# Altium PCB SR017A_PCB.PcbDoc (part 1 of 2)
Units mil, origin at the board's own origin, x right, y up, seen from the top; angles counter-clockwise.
Board outline 3000 x 2501 mil, 4 copper layers (Top Layer, GND Layer, Signal Layer, Bottom Layer), stack 59.4 mil thick; 53 components, 14 nets, 94 pads, 180 vias.
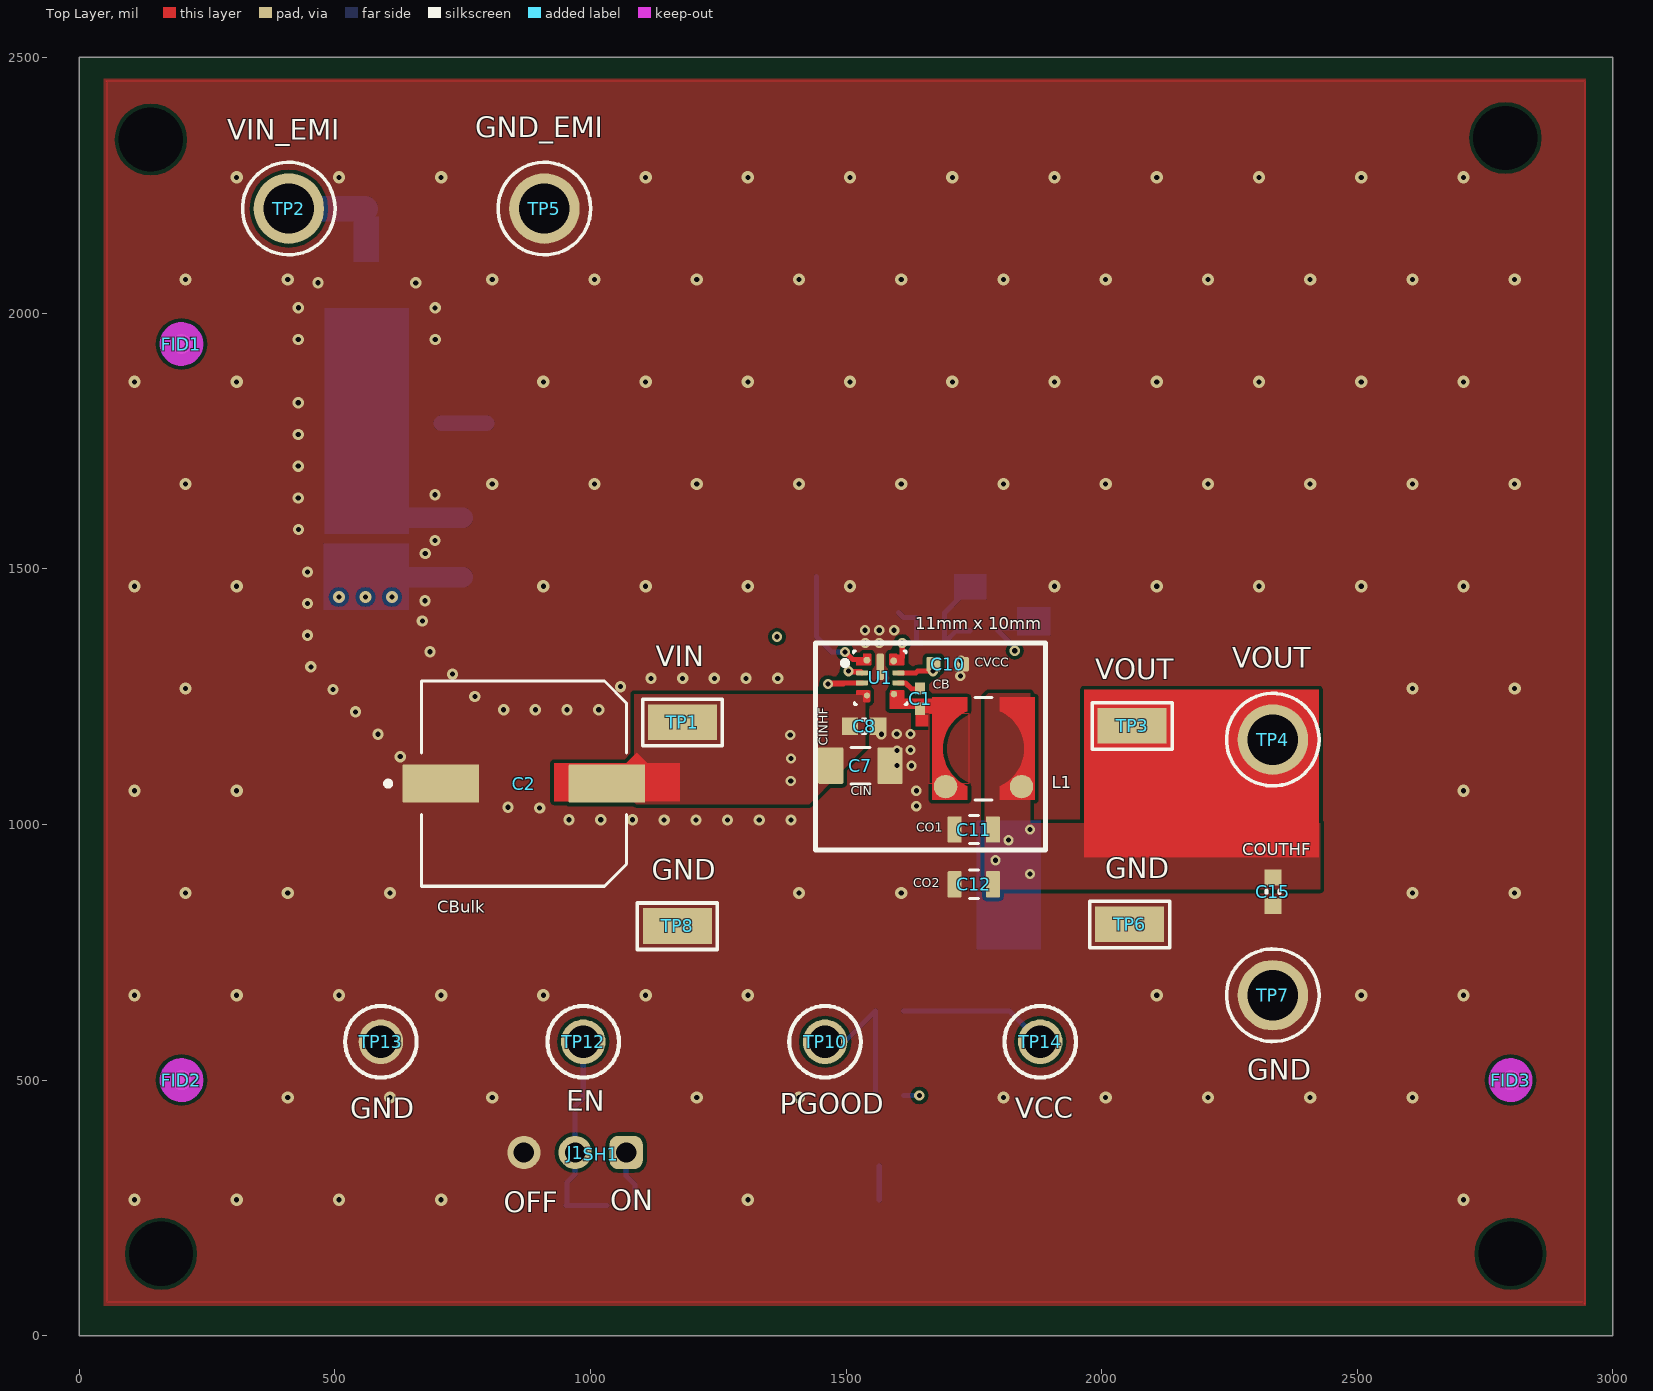
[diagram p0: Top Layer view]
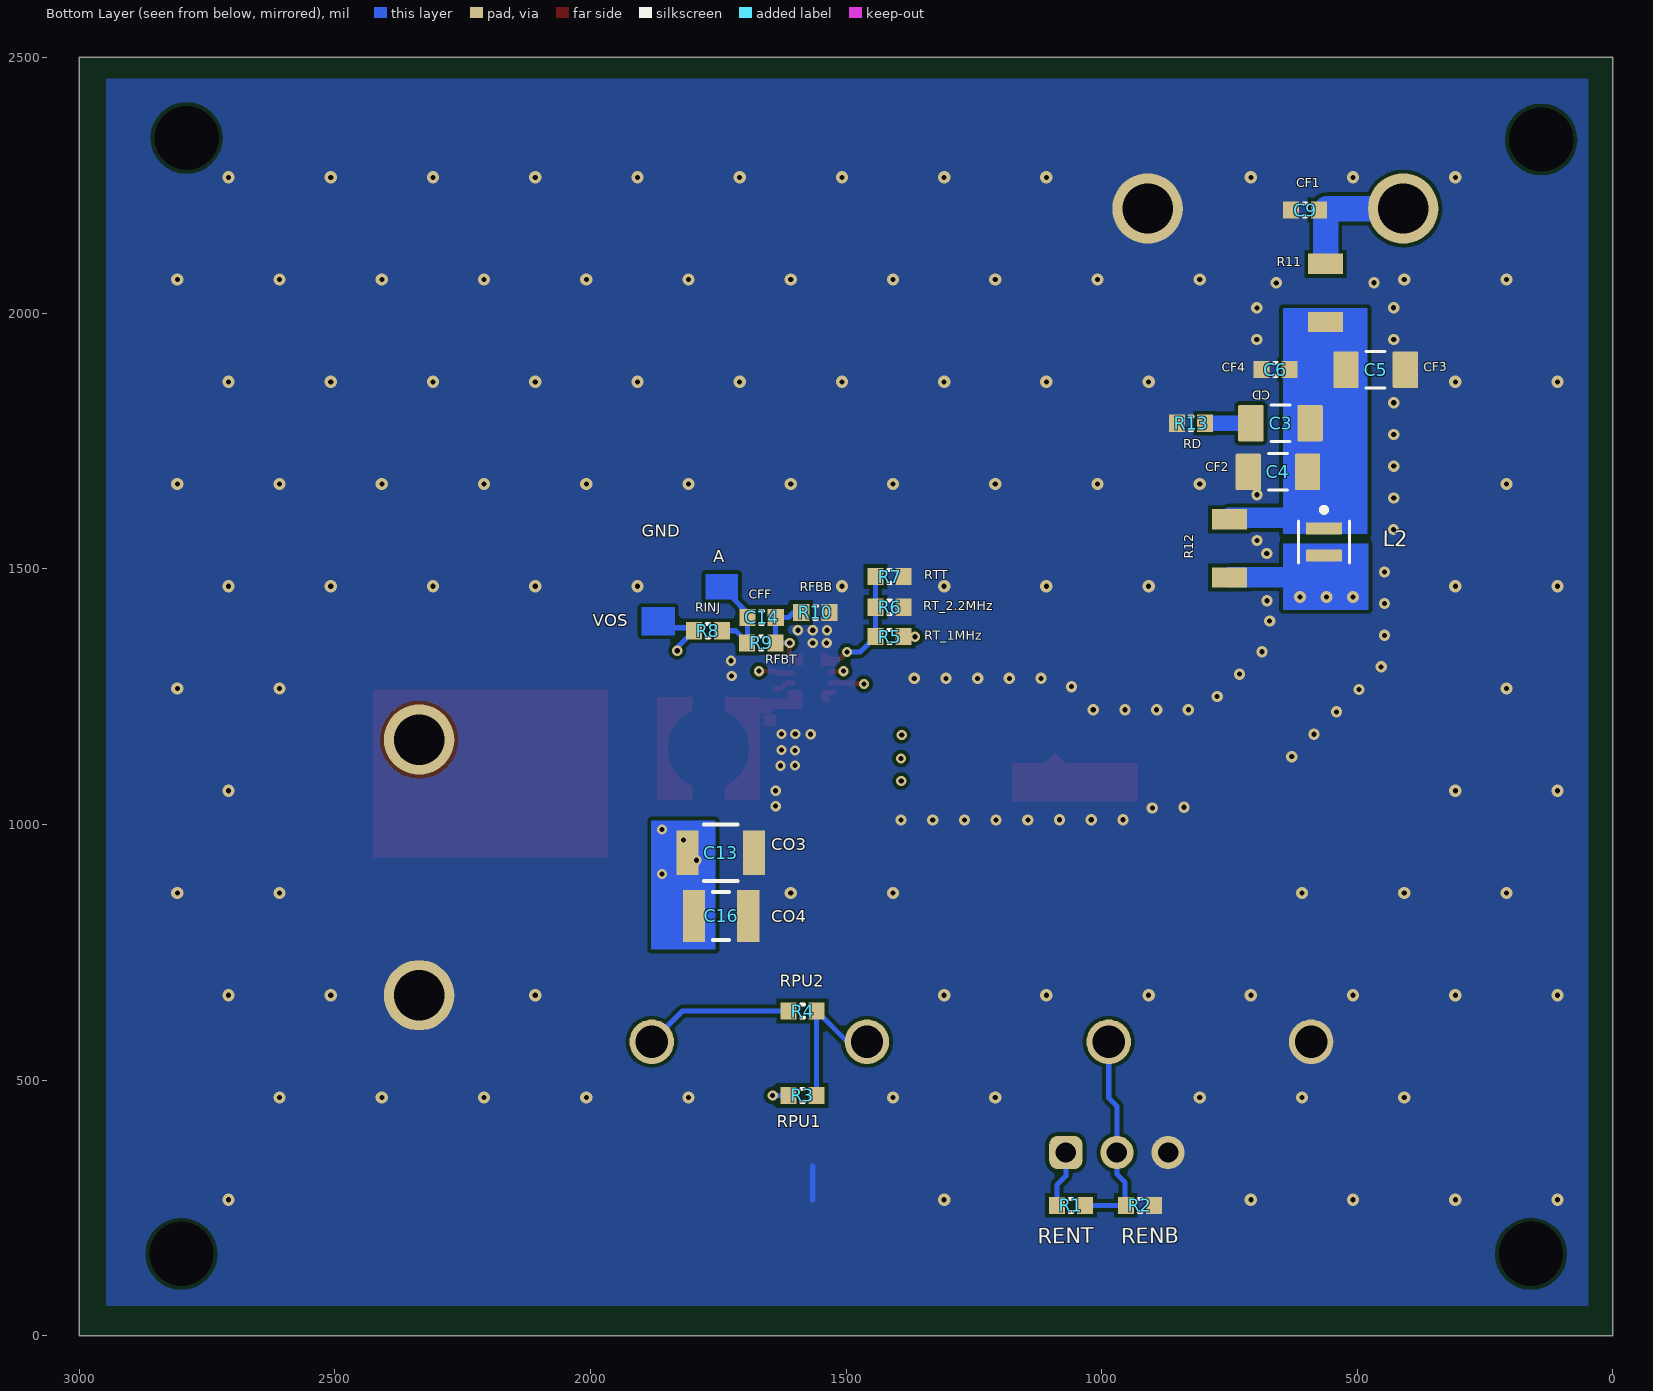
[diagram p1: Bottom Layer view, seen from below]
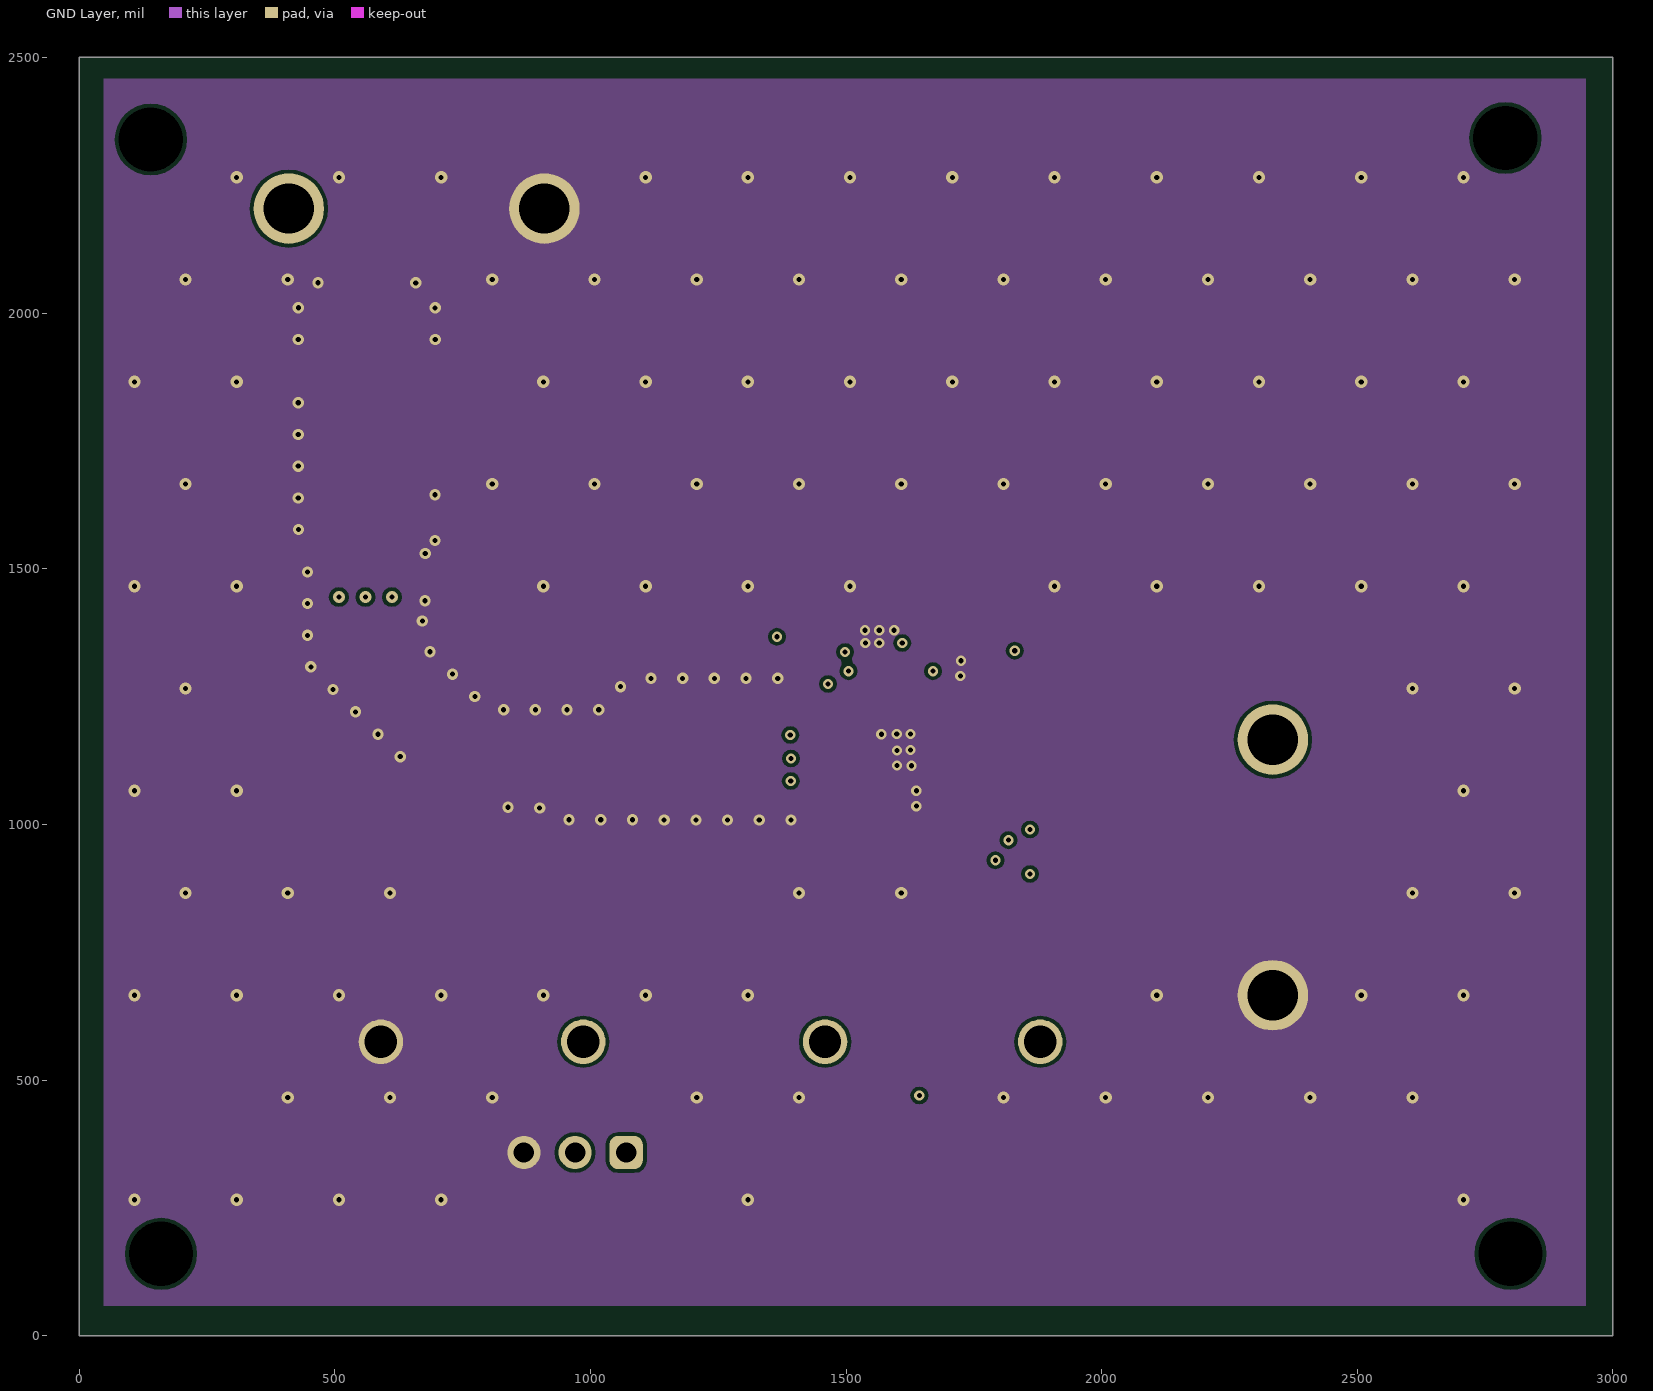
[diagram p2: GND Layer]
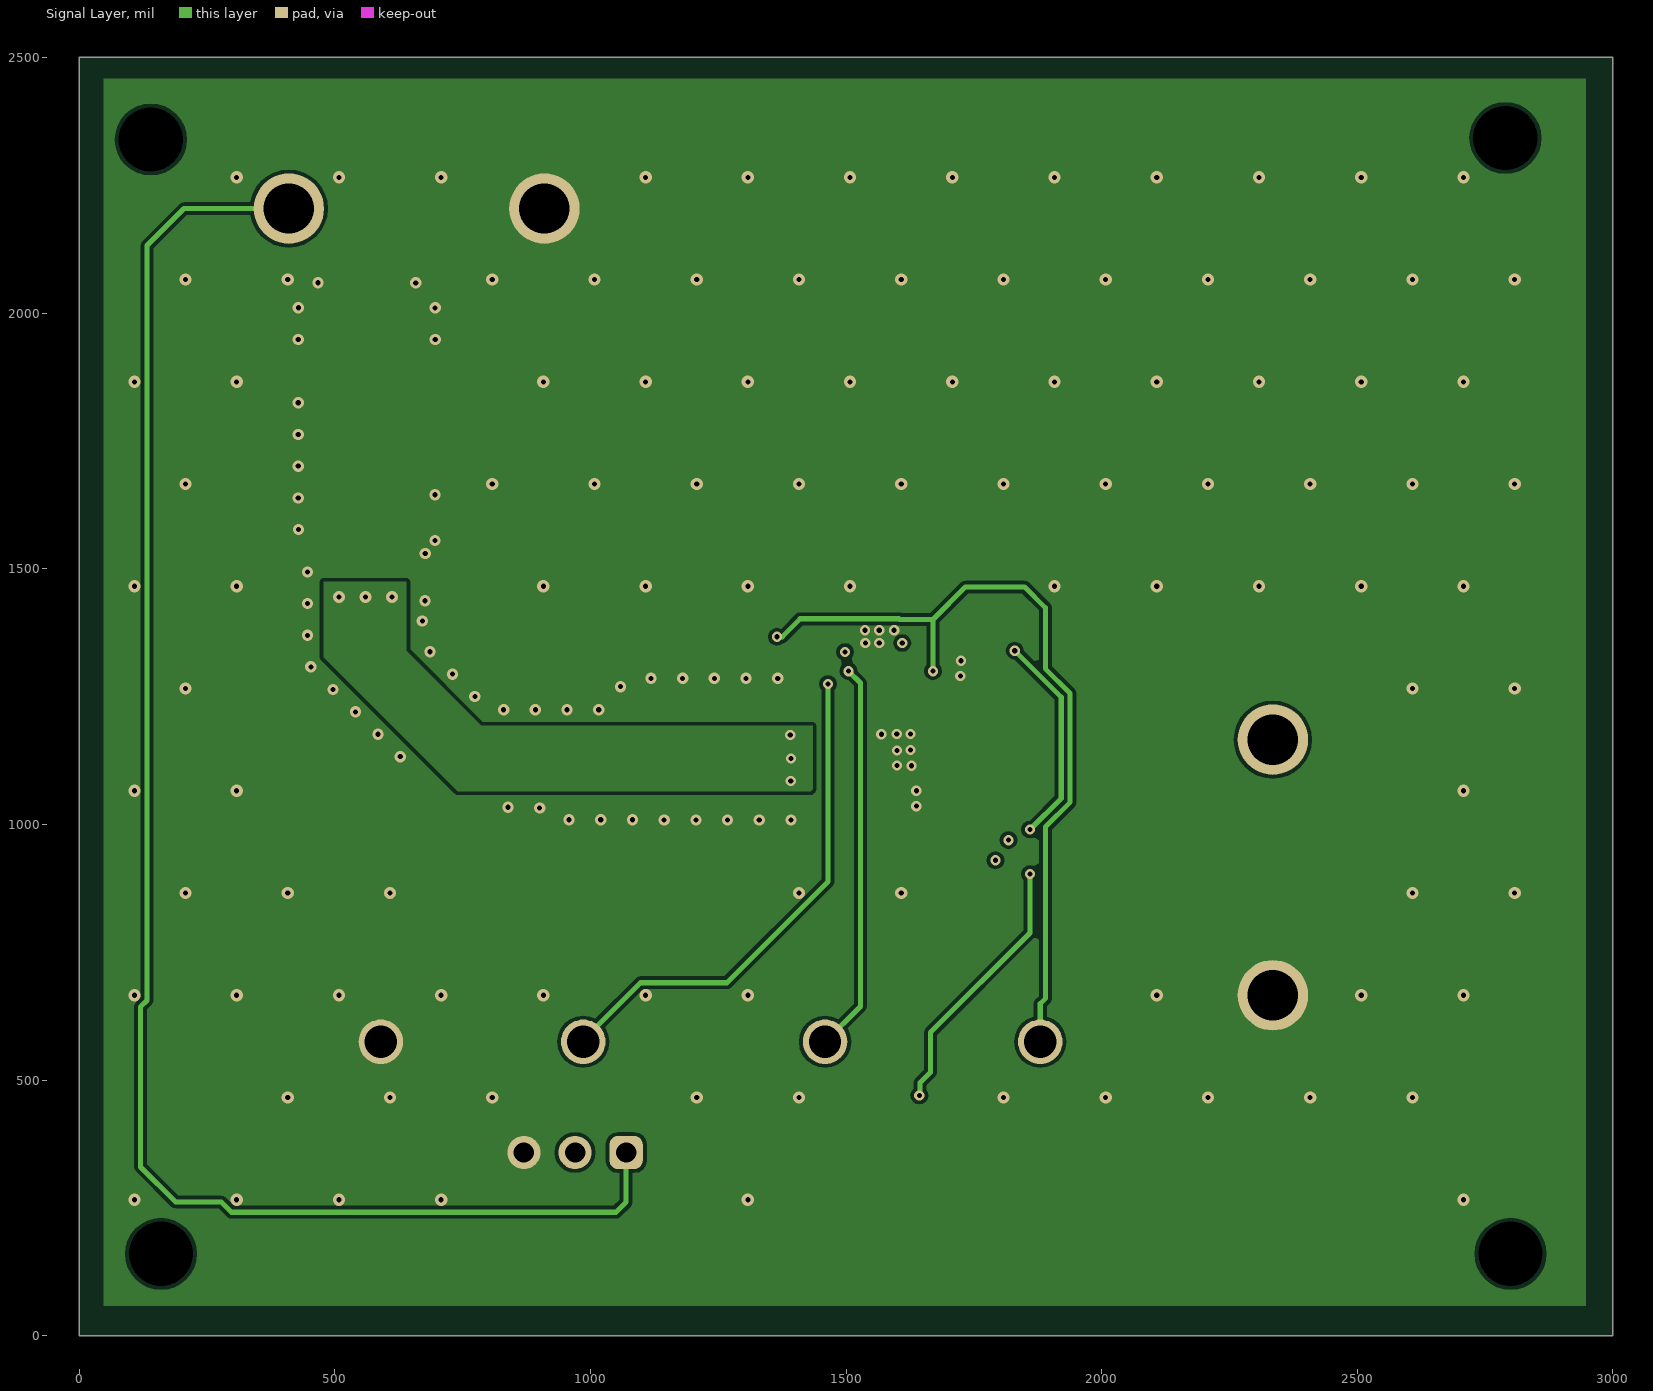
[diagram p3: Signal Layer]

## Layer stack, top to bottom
Top Solder: solder mask 0.4, Solder Resist, Dk 3.5
Top Layer: signal copper 2.8
Dielectric1: core 10, FR-4 High Tg, Dk 4.2
GND Layer: signal copper 1.4
Dielectric 2: prepreg 31, FR-4 High Tg, Dk 4.2
Signal Layer: signal copper 1.4
Dielectric 3: core 10, FR-4 High Tg, Dk 4.2
Bottom Layer: signal copper 2.8
Bottom Solder: solder mask 0.4, Solder Resist, Dk 3.5

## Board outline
0,0 0,2501 2999,2501 3000,2500 3000,0

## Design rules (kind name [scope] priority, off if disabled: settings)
AcuteAngle [All] p1: minimum=4.50000000000000E+0001 checktracksonly=FALSE
AssemblyTestPointUsage [All] p1: valid=2
BoardOutlineClearance BoardOutlineClearance_MountingHoles [OnCopper and InComponentClass('Mounting Holes')] p1: gap=40 ignorepadtopadclearanceinfootprint=FALSE
BoardOutlineClearance BoardOutlineClearance_Poly [OnCopper and IsPoly] p2: gap=25 ignorepadtopadclearanceinfootprint=FALSE
BoardOutlineClearance [OnCopper and Not InComponentClass('Logo') and not InComponentClass('FiducialMark') and not InRegion(1000,500,4000,800) and not InPoly] p3: gap=30 ignorepadtopadclearanceinfootprint=FALSE
Clearance Clearance_Keepouts [((IsTrack Or IsArc) And Not InPoly) And IsFree and IsKeepOut vs ((IsTrack Or IsArc) And Not InPoly) And IsFree and IsKeepOut] p1: gap=0 ignorepadtopadclearanceinfootprint=FALSE
Clearance Clearance_Poly [InPolygon] p2: gap=7 ignorepadtopadclearanceinfootprint=FALSE
Clearance Clearance_FiducialMark [IsKeepOut and InComponentClass('FiducialMark') vs IsPad and InComponentClass('FiducialMark')] p3: gap=0 ignorepadtopadclearanceinfootprint=FALSE
Clearance [All] p4: gap=7.5 ignorepadtopadclearanceinfootprint=FALSE except(0: Arc-Hole Track-Hole SMDPad-Hole THPad-Hole Via-Hole Fill-Hole Poly-Hole Region-Hole Text-Hole)
ComponentClearance ComponentClearance_MountingHoles_FiducialMarks [InComponentClass('Mounting Holes') vs InComponentClass('FiducialMark')] p1: gap=50 collisioncheckmode=3 verticalgap=10 showdistances=FALSE
ComponentClearance ComponentClearance_Shunt [InComponentClass('Header') vs InComponentClass('Shunt')] p2: gap=0 collisioncheckmode=3 verticalgap=0 showdistances=FALSE
ComponentClearance ComponentClearance_Logo [InComponentClass('Logo')] p3: gap=50 collisioncheckmode=3 verticalgap=10 showdistances=FALSE
ComponentClearance ComponentClearance_ScrewToNut [(HasFootprint('NY PMS 440 0025 PH')) vs (HasFootprint('Keystone_1902C'))] p4: gap=5 collisioncheckmode=3 verticalgap=10 showdistances=FALSE
ComponentClearance ComponentClearance_MountingHoles [InComponentClass('Mounting Holes')] p5: gap=250 collisioncheckmode=3 verticalgap=100000 showdistances=FALSE
ComponentClearance ComponentClearance_SmallPassives [HasFootprint('0201*') or HasFootprint('0402*') or HasFootprint('0508') or HasFootprint('0603*') or HasFootprint('0612') or HasFootprint('0805*') or HasFootprint('0815*') or HasFootprint('0830*') or HasFootprint('1206*') or HasFootprint('1210*') or HasFootprint('1808*') or HasFootprint('1812*') or HasFootprint('1825*') or HasFootprint('2010*') or HasFootprint('2220*') or HasFootprint('2225*') or HasFootprint('2512*') or HasFootprint('2728*') or HasFootprint('3518*') vs HasFootprint('0201*') or HasFootprint('0402*') or HasFootprint('0508') or HasFootprint('0603*') or HasFootprint('0612') or HasFootprint('0805*') or HasFootprint('0815*') or HasFootprint('0830*') or HasFootprint('1206*') or HasFootprint('1210*') or HasFootprint('1808*') or HasFootprint('1812*') or HasFootprint('1825*') or HasFootprint('2010*') or HasFootprint('2220*') or HasFootprint('2225*') or HasFootprint('2512*') or HasFootprint('2728*') or HasFootprint('3518*')] p6: gap=10 collisioncheckmode=3 verticalgap=10 showdistances=FALSE
ComponentClearance ComponentClearance_THtoSMT [IsThruComponent vs IsSMTComponent] p7: gap=40 collisioncheckmode=3 verticalgap=30 showdistances=FALSE
ComponentClearance ComponentClearance_THtoTH [IsThruComponent vs IsThruComponent] p8: gap=30 collisioncheckmode=3 verticalgap=30 showdistances=FALSE
ComponentClearance [All] p9: gap=10 collisioncheckmode=3 verticalgap=10 showdistances=FALSE
DiffPairsRouting [All] p1: maxlimit=100 minlimit=10 mostfreqgap=10 toplayer_minwidth=15 toplayer_maxwidth=15 toplayer_prefwidth=15 midlayer1_minwidth=15 midlayer1_maxwidth=15 midlayer1_prefwidth=15 midlayer2_minwidth=15 midlayer2_maxwidth=15 midlayer2_prefwidth=15 bottomlayer_minwidth=15 bottomlayer_maxwidth=15 bottomlayer_prefwidth=15 maxuncoupledlength=1000
FabricationTestPointUsage TestPointUsage [All] p1: valid=2 allowmultiple=FALSE
FabricationTestpoint Testpoint [All] p1: side=3 testpointundercomponent=TRUE minsize=40 maxsize=100 preferedsize=60 minholesize=0 maxholesize=40 preferedholesize=32 testpointgrid=1 allowsidetop=TRUE allowsidebottom=TRUE usegrid=TRUE gridtolerance=0.01
FanoutControl Fanout_LCC [IsLCC] p1: bgadir=Out bgaviamode=Centered fanoutstyle=Auto fanoutdirection=Alternating viagrid=1 // Fanout_LCC (Default Rule)
FanoutControl Fanout_BGA [IsBGA] p2: bgadir=Out bgaviamode=Centered fanoutstyle=Auto fanoutdirection=Alternating viagrid=1 // Fanout_BGA (Default Rule)
FanoutControl Fanout_Default [All] p4: bgadir=Out bgaviamode=Centered fanoutstyle=Auto fanoutdirection=Alternating viagrid=1 // Fanout_Default (Default Rule)
FanoutControl Fanout_Small [(CompPinCount < 5)] p5: bgadir=Out bgaviamode=Centered fanoutstyle=Auto fanoutdirection=OutThenIn viagrid=1 // Fanout_Small (Default Rule)
HoleSize [All] p1: absolutevalues=TRUE maxlimit=251 minlimit=7.87 maxpercent=80.000 minpercent=20.000
MinimumAnnularRing MinimumAnnularRing_ThermalPadVias [IsVia and InAnyComponent] p1: minimumring=5
MinimumAnnularRing [All] p2: minimumring=5
MinimumSolderMaskSliver MinimumSolderMaskSliver_Logo [InComponentClass('Logo') vs InComponentClass('Logo')] p1: minsoldermaskwidth=0.7
MinimumSolderMaskSliver [All] p2: minsoldermaskwidth=3.94
PlaneClearance [All] p1: clearance=8
PlaneConnect [All] p1: planeconnectstyle=Direct reliefexpansion=10 reliefentries=4 reliefconductorwidth=10 reliefairgap=10
PolygonConnect [All] p1: connectstyle=Direct reliefconductorwidth=10 reliefentries=4 polygonreliefangle="90 Angle" airgapwidth=10
RoutingVias ThermalPadVias [IsVia and InAnyComponent] p1: holewidth=8 width=16 viastyle="Through Hole" minholewidth=7.87 minwidth=10 maxholewidth=12.99 maxwidth=30
RoutingVias [All] p2: holewidth=8 width=16 viastyle="Through Hole" minholewidth=7.87 minwidth=15 maxholewidth=40 maxwidth=65
SilkToBoardRegionClearance [Not ((IsComment or IsDesignator) And (Hide <> 'False')) and not InRegion(1000,500,4000,800)] p1:
SilkToSilkClearance SilkToSilkClearance_Pb-FreeLogo [(HasFootprint('Pb-Free_Overlay_Medium') OR HasFootprint('Pb-Free_Overlay_Small')) vs (HasFootprint('Pb-Free_Overlay_Medium') OR HasFootprint('Pb-Free_Overlay_Small'))] p1: silktosilkclearance=0
SilkToSilkClearance [All] p2: silktosilkclearance=0
SilkToSolderMaskClearance SilkToComponentPadClearance [(IsPad or IsFill or IsRegion) and InAnycomponent] p1: minsilkscreentomaskgap=0 clearancetoexposedcopper=TRUE
SilkToSolderMaskClearance "Silk to Solder Mask Opening" [All] p2: minsilkscreentomaskgap=0 clearancetoexposedcopper=FALSE
SolderMaskExpansion [All] p1: expansion=1.97
Width [All] p1: maxlimit=100 minlimit=0.1 preferedwidth=10
14 further rules are at their usual default settings.

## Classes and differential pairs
component class Header: J1
component class FiducialMark: FID1 FID2 FID3
component class AssemblyNote: ZZ1 ZZ2 ZZ3 ZZ4
component class SR017A_sch: C1 C2 C3 C4 C5 C6 C7 C8 C9 C10 C11 C12 C13 C14 C15 C16 CVCC J1 L L1 L2 R1 R2 R3 R4 R5 R6 R7 R8 R9 R10 R11 R12 R13 R? SH1 TP1 TP2 TP3 TP4 TP5 TP6 TP7 TP8 TP10 TP12 TP13 TP14 U1
component class SR017A_Hardware: FID1 FID2 FID3 ZZ1 ZZ2 ZZ3 ZZ4
component class Shunt: SH1

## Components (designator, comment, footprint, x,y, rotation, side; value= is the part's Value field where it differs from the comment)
C1 "CB" 0402L 1644.8,1246.17 r90 top value=0.1uF
C2 "CBulk" FP-476SML100M_RADIAL-IPC_C 870,1080 r0 top value=47µF
C3 "CD" FP-CL31Y225KCHVPNE_1206-MFG 650,1785 r180 bottom value=2.2µF
C4 "CF2" FP-CL31Y225KCHVPNE_1206-MFG 655,1690 r180 bottom value=2.2µF
C5 "CF3" FP-CL31Y225KCHVPNE_1206-MFG 463.93,1889.7 r0 bottom value=2.2µF
C6 "CF4" 0603L 660,1890 r0 bottom value=0.1uF
C7 "CIN" FP-CL31Y225KCHVPNE_1206-MFG 1528.2,1115 r180 top value=2.2µF
C8 "CINHF" 0603L 1535.46,1192.13 r0 top value=0.1uF
C9 "CF1" 0603L 602,2202 r0 bottom value=0.1uF
C10 "CVCC" FP-C1608X7R1E105K080AE_0603-MFG 1698.81,1313.5 r180 top value=1µF
C11 "CO1" FP-GRM21BR71E225KE11L_0805-MFG 1750,990 r0 top value=2.2µF
C12 "CO2" FP-GRM21BR71E225KE11L_0805-MFG 1750,883.12 r0 top value=2.2µF
C13 "CO3" 1210_280 1745,945 r180 bottom value=10uF
C14 "CFF" 0603L 1665,1405 r180 bottom value=22pF
C15 "COUTHF" 0603L 2335,868.41 r90 top value=1000pF
C16 "CO4" 1210_270L 1744.48,821.16 r180 bottom value=22uF
FID1 "Fiducial" Fiducial10-20 200,1940 r0 top
FID2 "Fiducial" Fiducial10-20 200,500 r0 top
FID3 "Fiducial" Fiducial10-20 2800,500 r0 top
J1 "EN" TSW-103-07-G-S 970,358.35 r180 top
L1 "MSS5131-224MLC 220uH" FP-MSS5131-224MLC_SMT2_5MM1_5MM1-MFG 1769.07,1148.49 r90 top value=220uH
L2 "XFL2010-102MEC" FP-XFL2010-102MEC_SMT2_1MM9_2MM0-MFG 565,1552.59 r270 bottom value=1uH
R1 "RENT" 0603L 1060,255 r0 bottom value=787k
R2 "RENB" 0603L 925,255 r0 bottom value=100k
R3 "RPU1" 0603L 1585.32,470 r180 bottom value=100k
R4 "RPU2" 0603L 1585,635 r180 bottom value=100k
R5 "RT_1MHz" 0603L 1414.81,1367.49 r0 bottom value=0
R6 "RT_2.2MHz" 0603L 1414.89,1425 r0 bottom value=0
R7 "RTT" 0603L 1414.89,1485 r0 bottom value=30.1k
R8 "RINJ" 0603L 1770,1379.05 r0 bottom value=0
R9 "RFBT" 0603L 1665.82,1355.32 r0 bottom value=0
R10 "RFBB" 0603L 1560,1414.95 r0 bottom value=24.9k
R11 "RFILTJ" 5108 562,2040 r270 bottom value=0
R12 "RSHUNT" 5108 750,1540 r270 bottom value=0
R13 "RD" 0603L 825,1785 r180 bottom value=4.99
SH1 "SNT-100-BK-G" SNT-100-BK-G 1020.33,355 r180 top value=1x2
TP1 "VIN" Testpoint_Keystone_Miniature 1180,1200 r0 top
TP2 "VIN_EMI" Keystone1502-2 410,2205 r90 top
TP3 "VOUT" Testpoint_Keystone_Miniature 2059.87,1193.22 r0 top
TP4 "VOUT" Keystone1502-2 2335,1166 r270 top
TP5 "GND_EMI" Keystone1502-2 910,2205 r90 top
TP6 "GND" Testpoint_Keystone_Miniature 2055,805 r0 top
TP7 "GND" Keystone1502-2 2335,666 r90 top
TP8 "GND" Testpoint_Keystone_Miniature 1170,801.5 r0 top
TP10 "PGOOD" Keystone5012 1459,575 r90 top
TP12 "EN" Keystone5012 986,575 r90 top
TP13 "GND" Keystone5011 590,575 r90 top
TP14 "VCC" Keystone5012 1880,575 r90 top
U1 "LMR36500P5RPER" RPE0009B-MFG 1566.96,1286.89 r0 top
ZZ1 "This Assembly Note is for PCB labels only" AssemblyNoteLabel 60,3415 r0 top
ZZ2 "These assemblies are ESD sensitive, ESD precautions shall be observed." AssemblyNote 55,3255 r0 top
ZZ3 "These assemblies must be clean and free from flux and all contaminants. Use of no clean flux is not acceptable." AssemblyNote 55,3105 r0 top
ZZ4 "These assemblies must comply with workmanship standards IPC-A-610 Class 2, unless otherwise specified." AssemblyNote 60,2955 r0 top

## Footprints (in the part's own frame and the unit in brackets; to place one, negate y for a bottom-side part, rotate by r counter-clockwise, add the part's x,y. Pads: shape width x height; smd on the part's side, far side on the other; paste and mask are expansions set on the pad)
0402L [mm] "0402 from SM-752 data"
  rect 0.6x0.5 smd: 1(-0.5,0) 2(0.5,0)
  body extent -0.55,-0.3 0.55,0.3, height 0.6
0603L [mm] "0603 from SM-752 data"
  rect 0.8x0.85 smd: 1(-0.7,0) 2(0.7,0)
  silkscreen extent -0.07,-0.33 0.07,0.33, body extent -0.87,-0.47 0.87,0.47, height 1
1210_270L [mm] "1210"
  rect 1.1x2.6 smd: 1(-1.35,0) 2(1.35,0)
  silkscreen extent -0.4,-1.2 0.4,1.2, body extent -1.7,-1.35 1.7,1.35, height 2.7
1210_280 [mm] "SMD, 2-Leads, Body 3.6x2.8mm, Height 2.8mm"
  rect 1.1x2.2 smd: 1(-1.65,0) 2(1.65,0)
  silkscreen extent -0.84,-1.4 0.84,1.4, body extent -1.8,-1.4 1.8,1.4, height 2.8
5108 [mm] "Keystone"
  rect 1.01x1.73 smd: 1(-1.445,0) 2(1.445,0)
  body extent -1.52,-0.85 1.52,0.85, height 0.71
AssemblyNote [mil] "Assembly Note"
AssemblyNoteLabel [mil] "Assembly Note for PCB Labels"
Fiducial10-20 [mm]
  round 1 smd mask+0.5: 1(0,0)
  Top Layer keep-out circle w1.178: c0,0 r0.5
FP-476SML100M_RADIAL-IPC_C [mm]
  rrect5% 3.8x1.9 smd paste+0 mask+0: 1(-4.125,0) 2(4.125,0)
  silkscreen extent -6.87,-5.1 5.1,5.1, body extent -6.25,-5.35 6.25,5.35, height 0.25
FP-C1608X7R1E105K080AE_0603-MFG [mm]
  rrect14% 0.7x0.7 smd paste+0 mask+0: 1(-0.7,0) 2(0.7,0)
  body extent -1.15,-0.58 1.15,0.58, height 0.25
FP-CL31Y225KCHVPNE_1206-MFG [mm]
  rrect8% 1.25x1.8 smd paste+0 mask+0: 1(-1.475,0) 2(1.475,0)
  silkscreen extent -0.48,-0.9 0.48,0.9, body extent -1.6,-0.8 1.6,0.8, height 1.8
FP-GRM21BR71E225KE11L_0805-MFG [mm]
  rrect14% 0.7x1.3 smd paste+0 mask+0: 1(-0.95,0) 2(0.95,0)
  silkscreen extent -0.23,-0.7 0.23,0.7, body extent -1.4,-0.8 1.4,0.8, height 0.25
FP-MSS5131-224MLC_SMT2_5MM1_5MM1-MFG [mil]
  round 45.84 smd paste+0 mask+0: 1(-74.31,74.31) 2(-74.31,-74.31)
  Top Layer region: 100,-100 -100,-100 -100,-31.5 -73.24,-31.5 -51.28,-61.03 -18.4,-77.56 18.4,-77.56 51.28,-61.03 73.24,-31.5 73.24,-31.5 100,-31.5
  Top Layer region: -100,100 100,100 100,31.5 73.24,31.5 51.28,61.03 18.4,77.56 -18.4,77.56 -51.28,61.03 -73.24,31.5 -73.24,31.5 -100,31.5
  silkscreen extent -100,-17 100,17, body extent -104,-104 104,104, height 10
FP-XFL2010-102MEC_SMT2_1MM9_2MM0-MFG [mm]
  rrect17% 0.6x1.8 smd paste+0 mask+0: 1(-0.675,0) 2(0.675,0)
  silkscreen extent -1.72,-1.28 1.05,1.28, body extent -0.94,-0.99 0.94,0.99, height 1
Keystone1502-2 [mm] "Double Turret"
  round 3.5 hole 2.5: 1(0,0)
  silkscreen extent -2.3,-2.3 2.3,2.3, body extent -1.6,-1.6 1.59,1.6, height 5.62
Keystone5011 [mil] "Keystone Multipurpose loops"
  round 87 hole 63: 1(0,0)
  silkscreen extent -70,-70 70,70, body extent -63,-63 63,62, height 319
Keystone5012 [mil] "Keystone Multipurpose loops"
  round 87 hole 63: 1(0,0)
  silkscreen extent -70,-70 70,70, body extent -63,-63 63,62, height 319
RPE0009B-MFG [mm]
  round 0.342 smd paste-1000 mask+0: 1(-0.661,0.877)
  rrect40% 0.6x0.25 smd paste+0 mask+0: 2(-0.9,0.25) 3(-0.9,-0.25) 6(0.9,-0.25) 7(0.9,0.25)
  round 0.291 smd paste+0 mask+0: 4(-0.661,-0.877)
  round 0.323 smd paste+0 mask+0: 5(0.68,-0.805)
  round 0.346 smd paste-1000 mask+0: 8(0.665,0.841)
  rrect29% 0.35x1.3 smd paste-1000 mask+0: 9(0,0.55)
  Top Layer region: 1.2,0.8 1.193,0.825 1.175,0.844 1.15,0.85 1.15,0.85 0.9,0.851 0.881,0.854 0.865,0.865 0.854,0.881 0.85,0.901 0.85,0.901 0.85,1.15 0.843,1.175 0.825,1.193 0.8,1.2 0.8,1.2 0.5,1.2 0.481,1.196 0.465,1.185 0.454,1.169 0.45,1.15 0.45,1.15 0.45,0.676 0.454,0.656 0.465,0.64 0.481,0.629 0.5,0.626 0.5,0.625 1.15,0.626 1.169,0.629 1.185,0.64 1.196,0.656 1.2,0.676 1.2,0.676
  Top Layer region: 1.2,-0.8 1.193,-0.825 1.175,-0.844 1.15,-0.85 1.15,-0.851 0.9,-0.85 0.881,-0.854 0.865,-0.865 0.854,-0.881 0.85,-0.9 0.85,-0.901 0.85,-1.15 0.843,-1.175 0.825,-1.193 0.8,-1.2 0.8,-1.2 0.55,-1.2 0.531,-1.196 0.515,-1.185 0.504,-1.169 0.5,-1.15 0.5,-1.15 0.5,-0.676 0.504,-0.656 0.515,-0.64 0.531,-0.629 0.55,-0.625 0.55,-0.625 1.15,-0.626 1.169,-0.629 1.185,-0.64 1.196,-0.656 1.2,-0.676 1.2,-0.676
  Top Layer region: -1.2,-0.8 -1.193,-0.825 -1.175,-0.844 -1.15,-0.85 -1.15,-0.85 -0.9,-0.851 -0.881,-0.854 -0.865,-0.865 -0.854,-0.881 -0.85,-0.901 -0.85,-0.901 -0.85,-1.15 -0.843,-1.175 -0.825,-1.193 -0.8,-1.2 -0.8,-1.2 -0.55,-1.2 -0.531,-1.196 -0.515,-1.185 -0.504,-1.169 -0.5,-1.15 -0.5,-1.15 -0.5,-0.676 -0.504,-0.656 -0.515,-0.64 -0.531,-0.629 -0.55,-0.626 -0.55,-0.625 -1.15,-0.626 -1.169,-0.629 -1.185,-0.64 -1.196,-0.656 -1.2,-0.676 -1.2,-0.676
  Top Layer region: -1.2,0.8 -1.193,0.825 -1.175,0.844 -1.15,0.85 -1.15,0.851 -0.9,0.851 -0.881,0.854 -0.865,0.865 -0.854,0.881 -0.85,0.901 -0.85,0.901 -0.85,1.15 -0.843,1.175 -0.825,1.193 -0.8,1.2 -0.8,1.2 -0.5,1.2 -0.481,1.196 -0.465,1.185 -0.454,1.169 -0.45,1.15 -0.45,1.15 -0.45,0.676 -0.454,0.656 -0.465,0.64 -0.481,0.629 -0.5,0.626 -0.5,0.625 -1.15,0.626 -1.169,0.629 -1.185,0.64 -1.196,0.656 -1.2,0.676 -1.2,0.676
  silkscreen extent -1.87,-1.33 1.33,1.33, body extent -1.3,-1.3 1.3,1.3, height 0.25
SNT-100-BK-G [mil] "Samtec STEP model"
  round 1 on Mech3: 0(0,0)
  body extent -100,-50 100,50, height 344
Testpoint_Keystone_Miniature [mil] "Miniature SMT test point"
  rect 135x70 smd: 1(0,0)
  silkscreen extent -78,-46 78,45, body extent -52,-20 52,20, height 61
TSW-103-07-G-S [mm] "Samtec 100mil, 1x3, 230 mil above insulator"
  rrect50% 1.65x1.65 hole 1.016: 1(-2.54,0)
  round 1.65 hole 1.016: 2(0,0) 3(2.54,0)
  body extent -3.81,-1.27 3.81,1.27, height 8.38

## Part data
C1: library part CMP-0080610-1, "CAP, CERM, 0.1 µF, 25 V,+/- 10%, X7R, AEC-Q200 Grade 1, 0402", Cap_Case=0402, Manufacturer=TDK, PartNumber=CGA2B3X7R1E104K050BB, Supplier Part Number 1=445-6902-1-ND, TempCo=X7R, Tolerance_%=10%, Value2=25V, ValueDisplayed=0.1µF
C2: library part CMP-0095711-1, "47 µF 100 V Aluminum Electrolytic Capacitors Radial, Can - SMD 3.5274Ohm @ 120Hz 2000 Hrs @ 85°C", Digikey Part Number=1572-1483-1-ND, Leakage Current=47uA, Manufacturer="Cornell Dubilier", Mouser Part Number=598-476SML100M, Operating Temperature Range="-40°C to +85°C", Part Number=476SML100M, Tolerance_%=20%, ValueDisplayed=47uF
C3 C4 C5 C7: library part CMP-0001547-1, "Cap Ceramic 2.2uF 100V X7S 10% SMD 1206 125°C Emboss T/R", Digikey Part Number=1276-CL31Y225KCHVPNECT-ND, Manufacturer=Samsung, Mouser Part Number=187-CL31Y225KCHVPNE, Operating Temperature Range="-55°C to +125°C", Part Number=CL31Y225KCHVPNE, TempCo=22%, Temperature Characteristic=X7S, Tolerance_%=10%, ValueDisplayed=2.2uF
C6 C8 C9: library part CMP-0007469-4, "CAP, CERM, 0.1 uF, 100 V, +/- 10%, X7R, 0603", Cap_Case=0603, Manufacturer=MuRata, PartNumber=GRM188R72A104KA35D, Supplier Part Number 1=490-3285-1-ND, TempCo=X7R, Tolerance_%=10%, Value1=Unknown, Value2=100V, ValueDisplayed=0.1uF
C10: library part CMP-0116394-1, "C Series 0603 1 uF 25 V ±10 %Tolerance X7R SMT Multilayer Ceramic Capacitor", Digikey Part Number=445-173615-1-ND, Manufacturer=TDK, Mouser Part Number=810-C1608X7R1E105KAE, Operating Temperature Range="-55°C to +125°C", Part Number=C1608X7R1E105K080AE, TempCo=15%, Temperature Characteristic=X7R, Tolerance_%=10%, ValueDisplayed=1uF
C11 C12: library part CMP-0001537-1, "Chip Multilayer Ceramic Capacitors for General Purpose, 0805, 2.2uF, X7R, 15%, 10%, 25V", Manufacturer=Murata, Operating Temperature Range="-55°C to +125°C", Part Number=GRM21BR71E225KE11L, TempCo=15%, Temperature Characteristic=X7R, Tolerance_%=10%, ValueDisplayed=2.2uF
C13: library part CMP-0009078-1, "CAP, CERM, 10 uF, 25 V, +/- 10%, X7R, 1210", Cap_Case=1210, Manufacturer=Kemet, PartNumber=C1210C106K3RACTU, Supplier Part Number 1=399-8224-1-ND, TempCo=X7R, Tolerance_%=10%, Value1=Unknown, Value2=25V, ValueDisplayed=10uF
C14: library part CMP-0006775-2, "CAP, CERM, 22 pF, 50 V, +/- 5%, C0G/NP0, 0603", Cap_Case=0603, Manufacturer=AVX, PartNumber=06035A220JAT2A, Supplier Part Number 1=478-1167-1-ND, TempCo=C0G/NP0, Tolerance_%=5%, Value1="0.259 ohm", Value2=50V, ValueDisplayed=22pF
C15: library part CMP-0007467-4, "CAP, CERM, 1000 pF, 100 V, +/- 10%, X7R, 0603", Cap_Case=0603, Manufacturer=MuRata, PartNumber=GRM188R72A102KA01D, Supplier Part Number 1=490-1472-1-ND, TempCo=X7R, Tolerance_%=10%, Value1=Unknown, Value2=100V, ValueDisplayed=1000pF
C16: library part CMP-0009224-2, "CAP, CERM, 22 uF, 25 V, +/- 10%, X7R, 1210", Cap_Case=1210, Manufacturer=MuRata, PartNumber=GRM32ER71E226KE15L, Supplier Part Number 1=490-5313-1-ND, TempCo=X7R, Tolerance_%=10%, Value1=Unknown, Value2=25V, ValueDisplayed=22uF
FID1 FID2 FID3: library part CMP-0077181-1, "Fiducial mark.  There is nothing to buy or mount.", Manufacturer=N/A
J1: library part CMP-0075407-2, "Header, 100mil, 3x1, Gold, TH", Color=Black, Current_A=6.3A, Manufacturer=Samtec, PartNumber=TSW-103-07-G-S, Supplier Part Number 1=SAM1029-03-ND, Voltage_V=550V
L1: library part CMP-0001415-1, "Power Inductors - SMD 220uH Shld 20% 0.5A 1.1ohms AEC-Q200", Manufacturer=Coilcraft, Mouser Part Number=994-MSS5131-224MLC, Operating Temperature Range=to, Part Number=MSS5131-224MLC, Self Resonant Frequency=8MHz, Test Frequency=100kHz, Tolerance_%=20%
L2: library part CMP-0001495-1, "1 µH Shielded Inductor 1.3 A 83mOhm Max Nonstandard", Digikey Part Number=2457-XFL2010-102MEC-ND, Manufacturer=Coilcraft, Mouser Part Number=994-XFL2010-102MEC, Operating Temperature Range=to, Self Resonant Frequency=130MHz, Test Frequency=1MHz, Tolerance_%=20%
R1: library part CMP-0023273-4, "RES, 787 k, 1%, 0.1 W, 0603", Manufacturer=Yageo, PartNumber=RC0603FR-07787KL, Power_W=100mW, Supplier Part Number 1=311-787KHRCT-ND, TempCo="100 ppm/C", Tolerance_%=1%, Value2=0.1W, Value_Code=787k
R2 R3 R4: library part CMP-0022735-5, "RES, 100 k, 1%, 0.1 W, 0603", Manufacturer=Yageo, PartNumber=RC0603FR-07100KL, Power_W=100mW, Supplier Part Number 1=311-100KHRCT-ND, TempCo="100 ppm/C", Tolerance_%=1%, Value2=0.1W, Value_Code=100k
R5 R6 R8 R9: library part CMP-0023343-2, "RES, 0, 1%, 0.1 W, AEC-Q200 Grade 0, 0603", Manufacturer="Stackpole Electronics Inc", PartNumber=RMCF0603ZT0R00, Power_W=100mW, Supplier Part Number 1=RMCF0603ZT0R00CT-ND, TempCo=ppm/C, Tolerance_%=1%, Value2=0.1W, Value_Code=0
R7: library part CMP-0023018-5, "RES, 30.1 k, 1%, 0.1 W, 0603", Manufacturer=Yageo, PartNumber=RC0603FR-0730K1L, Power_W=100mW, Supplier Part Number 1=311-30.1KHRCT-ND, TempCo="100 ppm/C", Tolerance_%=1%, Value2=0.1W, Value_Code=30k1, ValueDisplayed=30.1k
R10: library part CMP-0022237-1, "RES, 24.9 k, 1%, 0.1 W, 0603", Manufacturer=Vishay-Dale, PartNumber=CRCW060324K9FKEA, Power_W=100mW, Supplier Part Number 1=541-24.9KHCT-ND, TempCo="100 ppm/C", Tolerance_%=1%, Value2=0.1W, Value_Code=24k9, ValueDisplayed=24.9k
R11 R12: library part CMP-0016567-2, "RES, 0, 1%, 0.5 W, 1206", Manufacturer=Keystone, PartNumber=5108, Power_W=500mW, Supplier Part Number 1=36-5108CT-ND, TempCo=ppm/C, Tolerance_%=1%, Value2=0.5W, Value_Code=0
R13: library part CMP-0022478-4, "RES, 4.99, 1%, 0.1 W, AEC-Q200 Grade 0, 0603", Manufacturer=Vishay-Dale, PartNumber=CRCW06034R99FKEA, Power_W=100mW, Supplier Part Number 1=541-4.99HHCT-ND, TempCo="100 ppm/C", Tolerance_%=1%, Value2=0.1W, Value_Code=4R99, ValueDisplayed=4.99
SH1: library part CMP-0003623-3, "Shunt, 100mil, Gold plated, Black", Alternate Manufacturer=3M, Alternate PartNumber=969102-0000-DA, Manufacturer=Samtec, Supplier Part Number 1=SAM8858-ND
TP1 TP3 TP6 TP8: library part CMP-0055152-1, "Test Point, Miniature, SMT", Manufacturer=Keystone, PartNumber=5015, Supplier Part Number 1=36-5015TR-ND
TP2 TP4 TP5 TP7: library part CMP-0055113-1, "Terminal, Turret, TH, Double", Manufacturer=Keystone, PartNumber=1502-2, Supplier Part Number 1=36-1502-2-ND
TP10 TP12 TP14: library part CMP-0055149-1, "Test Point, Multipurpose, White, TH", Color=White, Manufacturer=Keystone, PartNumber=5012, Supplier Part Number 1=36-5012-ND
TP13: library part CMP-0055148-1, "Test Point, Multipurpose, Black, TH", Color=Black, Manufacturer=Keystone, PartNumber=5011, Supplier Part Number 1=36-5011-ND
U1: library part CMP-0001448-1, "3-V to 65-V, 50-mA Wide VIN Synchronous Buck Converter Optimized for Size and Light Load Efficiency", Manufacturer="Texas Instruments", Max Supply Voltage=65V, Min Supply Voltage=3V, Nominal Supply Current=4uA, Operating Temperature Range="-40°C to +150°C", Switching Frequency=200-2200kHz
ZZ1: library part CMP-0003616-3
ZZ2: library part CMP-0077236-1
ZZ3: library part CMP-0077237-1
ZZ4: library part CMP-0077238-1

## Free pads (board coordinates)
  round 60 hole 126: 1(140,2340) 1(160,160) 1(2790,2343) 1(2800,160)

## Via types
v1: diameter 24, hole 10, Top Layer to Bottom Layer, tented both sides, 102 vias
v2: diameter 22, hole 10, Top Layer to Bottom Layer, tented both sides, 47 vias
v3: diameter 20, hole 10, Top Layer to Bottom Layer, tented both sides, 23 vias
v4: diameter 20, hole 10, Top Layer to Bottom Layer, 8 vias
